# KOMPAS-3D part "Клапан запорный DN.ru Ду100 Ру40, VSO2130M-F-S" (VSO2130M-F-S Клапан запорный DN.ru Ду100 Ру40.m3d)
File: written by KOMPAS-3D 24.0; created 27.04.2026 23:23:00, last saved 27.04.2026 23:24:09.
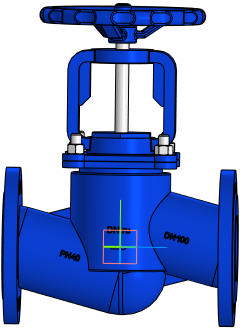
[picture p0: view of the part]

Document properties: Автор: DN.ru; Полное имя файла: C:\Работа\ГОТОВЫЕ ИСХОДНИКИ\VSO2130M-F-S Клапан запорный сальниковый DN.ru Ду15-100 Ру40\DN100\VSO2130M-F-S Клапан запорный DN.ru Ду100 Ру40.m3d

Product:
- Part/product: Клапан запорный DN.ru Ду100 Ру40  | designation VSO2130M-F-S
    Масса: 44
    Раздел спецификации: Прочие изделия
    Примечание: D090-01987

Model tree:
1. Операция без истории:1

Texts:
  VSO2130M-F-S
